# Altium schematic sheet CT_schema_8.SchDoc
size 254 x 194 mm
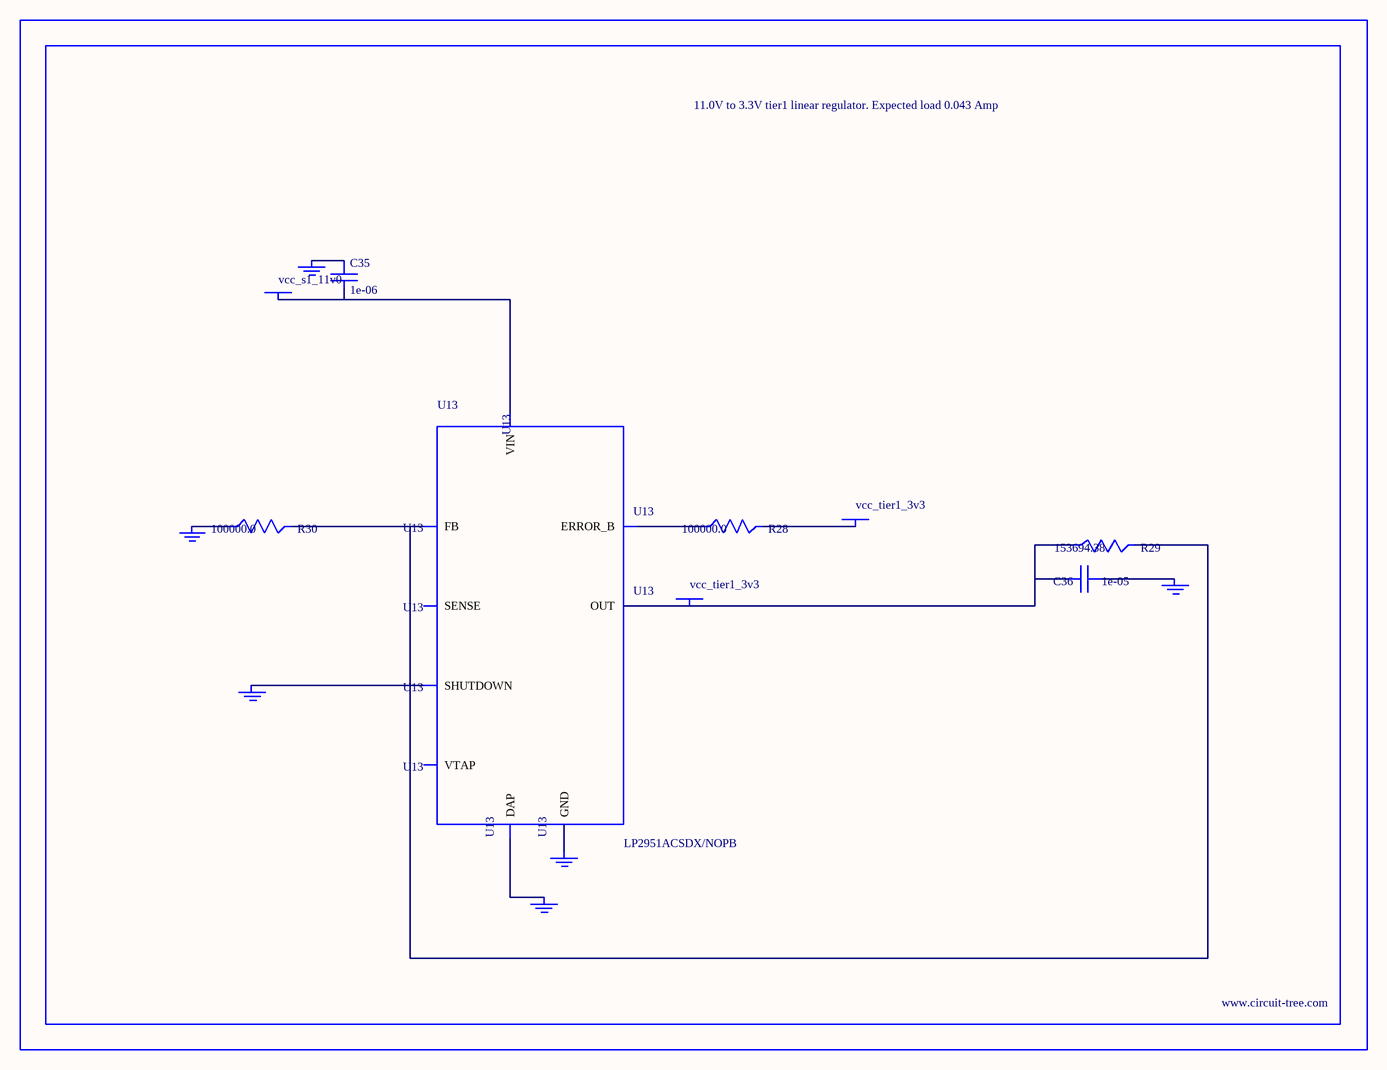
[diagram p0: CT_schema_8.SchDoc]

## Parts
BORDER7  (no value)
C35  1e-06  [C0603]
C36  1e-05  [C1210]
GND_INSTANCE_7_0  (no value)
GND_INSTANCE_7_1  (no value)
GND_INSTANCE_7_2  (no value)
GND_INSTANCE_7_3  (no value)
GND_INSTANCE_7_4  (no value)
GND_INSTANCE_7_5  (no value)
POWER_INSTANCE_7_0  vcc_tier1_3v3
POWER_INSTANCE_7_1  vcc_s1_11v0
POWER_INSTANCE_7_2  vcc_tier1_3v3
R28  100000.0  [R0603]
R29  153694.38  [R0603]
R30  100000.0  [R0603]
U13  LP2951ACSDX/NOPB  [WSON-8]

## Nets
NetC35_1: C35.1 GND_INSTANCE_7_3.0(GND)
NetC35_2: C35.2 POWER_INSTANCE_7_1.0(PWR) U13.8(VIN)
NetC36_1: C36.1 GND_INSTANCE_7_0.0(GND)
NetC36_2: C36.2 POWER_INSTANCE_7_2.0(PWR) R29.1 U13.1(OUT)
NetGND_INSTANCE_7_1_0: GND_INSTANCE_7_1.0(GND) U13.3(SHUTDOWN)
NetGND_INSTANCE_7_2_0: GND_INSTANCE_7_2.0(GND) R30.1
NetGND_INSTANCE_7_4_0: GND_INSTANCE_7_4.0(GND) U13.PAD(DAP)
NetGND_INSTANCE_7_5_0: GND_INSTANCE_7_5.0(GND) U13.4(GND)
NetPOWER_INSTANCE_7_0_0: POWER_INSTANCE_7_0.0(PWR) R28.2
NetR28_1: R28.1 U13.5(ERROR_B)
NetR29_2: R29.2 R30.2 U13.7(FB)

Not connected (* = marked no-connect by the designer): U13 2(SENSE) 6(VTAP)

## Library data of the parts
BORDER7 = BORDER_PAGE7
C35 = C0603C105K3RACTU
C36 = GRM32DR61E106MA12L
GND_INSTANCE_7_0-GND_INSTANCE_7_5 = GND
POWER_INSTANCE_7_0-POWER_INSTANCE_7_2 = PWR
R28 R30 = RC0603JR-07100KL
R29 = R29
